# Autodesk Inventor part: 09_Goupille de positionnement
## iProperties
Created: 2000-12
Part Number: 09_Goupille de positionnement
Material: Par défaut
Document SubType Name: Modélisation
Control State: 0
Master: False
Checked Out: False
Shininess: 20.0
Density: 0.0
Volumn: 0.0
Area: 0.0
PropertySet Name: Model Information
Author: Administrateur
